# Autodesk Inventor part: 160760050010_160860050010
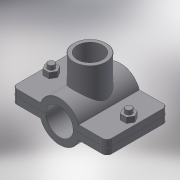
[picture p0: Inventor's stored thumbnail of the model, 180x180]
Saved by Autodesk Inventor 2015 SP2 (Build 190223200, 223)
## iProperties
Created: 2017-05
Part Number: 160760050010_160860050010
Material: Generic
Description: PLASSON SADDLE 50-1"
Document SubType Name: Modeling
Designer: KIM
Density: 1 g/cm^3
Appearance: Default
Author: KIM
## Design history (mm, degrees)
derived "16076.ipt"
feature "Solid1::16076.ipt"
feature "Solid2::16076.ipt"
tag "TaggingFeature1"
body "Solid1"
other parameters: "d1" = 106, "d2" = 25, "d4" = 73, "d5" = 0, "d6" = 5.3, "d7" = 106, "d8" = 0.1, "d10" = 0, "d11" = 0.5, "d14" = 39.3783, "d20" = 0.5, "d23" = 0.5, "d37" = 8, "d38" = 33, "d39" = 0, "d40" = 3, "d41" = 5, "d42" = 0, "d43" = 6, "d44" = 3, "d45" = 0, "d46" = 0.5, "d51" = 54, "d52" = 30.291, "d53" = 21, "d54" = 0, "d55" = 25, "d57" = 0, "d58" = 54, "d60" = 0, "d63" = 36.5, "d66" = 0, "B_" = 25, "G_" = 30.291, "A_" = 54, "L_" = 106, "L_1" = 73, "l_2" = 21
